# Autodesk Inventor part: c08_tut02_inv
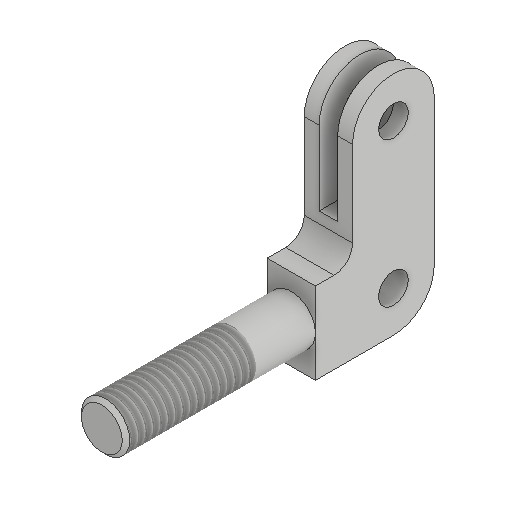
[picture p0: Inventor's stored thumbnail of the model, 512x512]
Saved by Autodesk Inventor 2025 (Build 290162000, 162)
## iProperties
Created: 2015-03
Part Number: c08_tut02_inv
Material: Generic
Document SubType Name: Modeling
Designer: Sandeep
Density: 1 g/cm^3
Appearance: Default
Author: Sandeep
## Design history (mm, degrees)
sketch "Sketch1"
  geometry: L1 (0, 0)-(0, 22); L2 (0, 22)-(5, 22); L3 (10, 27)-(10, 50); L4 (32, 50)-(32, 11); L5 (21, 0)-(0, 0); A1 r 11 centre (21, 50) between (32, 50) and (10, 50); A2 r 11 centre (21, 11) between (21, 0) and (32, 11); A3 r 5 centre (5, 27) between (5, 22) and (10, 27)
  constraints: 10 end point, 6 point on circle, 6 tangent, 3 centre point, 3 perpendicular, 1 parallel, 1 vertical
  dimensions: "d0" = 11 radius of A1; "d1" = 11 radius of A2; "d2" = 5 radius of A3; "d3" = 32 distance between parallel lines of L1 L4; "d4" = 22 distance between parallel lines of L5 L2; "d5" = 50 distance from line of A1.centre L5
extrude "Extrusion1" new body sketch "Sketch1" stored distance "d6" = 13; taper "d7" = 0 deg
hole "Hole1" diameter "d10" = 8; stored, may be unused: countersink angle "d14" = 90 deg, drill point angle "d16" = 118 deg; dims "d8" = 10, "d9" = 10, "d11" = 6, "d12" = 4, "d13" = 2, "d15" = 8
hole "Hole2" diameter "d19" = 8; stored, may be unused: countersink angle "d23" = 90 deg, drill point angle "d25" = 118 deg; dims "d17" = 10, "d18" = 10, "d20" = 6, "d21" = 4, "d22" = 2, "d24" = 8
sketch "Sketch2"
  geometry: L1 (0, -11)-(13, -11) reference; L2 (4, -11)-(4, 20); L3 (4, 20)-(9, 20); L4 (9, 20)-(9, -11); L5 (6.5, 50)-(6.5, -21.602); L6 (13, 50)-(0, 50) reference; L7 (9, -11)-(4, -11)
  constraints: 10 end point, 2 perpendicular, 2 point on line, 2 vertical, 1 collinear, 1 other
  dimensions: "d26" = 5 distance between parallel lines of L4 L2; "d27" = 30 distance between parallel lines of L6 L3
extrude "Extrusion2" cut sketch "Sketch2" extent not by distance; stored distance "d28" = 13; taper "d29" = 0 deg
sketch "Sketch3"
  geometry: L1 (13, 0)-(0, 0) reference; L2 (6.5, 0)-(6.5, 35.061); C1 r 6.5 at (6.5, 11)
  constraints: 2 end point, 1 centre point, 1 point on line, 1 vertical
  dimensions: "d30" = 13 diameter of C1; "d31" = 11 distance from line of C1.centre L1
extrude "Extrusion3" join sketch "Sketch3" distance "d32" = 51; taper "d33" = 0 deg
chamfer "Chamfer1" distance "d34" = 1; stored, may be unused: second distance "d35" = 2, angle "d36" = 45 deg
thread "Thread1" dims "d37" = 34, "d38" = 0
body "Solid1"
